// Mitsubishi GX Works2 project: 48.先进先出命令（SFWR,SFRD）   PLC: FX3U/FX3UC

PROGRAM MAIN
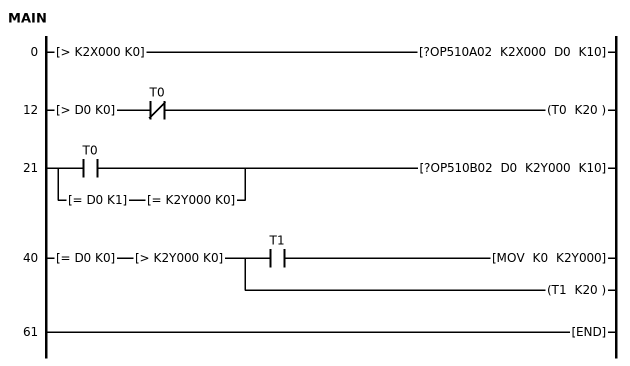
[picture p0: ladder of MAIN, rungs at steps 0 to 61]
0     LD>     K2X000 K0
      ?OP510A02 K2X000 D0 K10
12    LD>     D0 K0
      ANI     T0
      OUT     T0 K20
21    LD      T0
      LD=     D0 K1
      AND=    K2Y000 K0
      ORB
      ?OP510B02 D0 K2Y000 K10
40    LD=     D0 K0
      AND>    K2Y000 K0
      MPS
      AND     T1
      MOV     K0 K2Y000
      MPP
      OUT     T1 K20
61    END
END_PROGRAM
